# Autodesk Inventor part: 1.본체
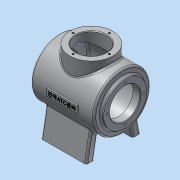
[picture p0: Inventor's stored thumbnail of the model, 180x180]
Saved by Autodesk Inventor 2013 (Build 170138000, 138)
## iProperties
Created: 2015-01
Part Number: 1.본체
Material: 알루미늄 6061
Document SubType Name: Modeling
Designer: dgall
Density: 2.71 g/cm^3
Mass: 1020.74 g
Surface Area: 1061.21 cm^2
Volume: 376.657 cm^3
Author: dgall
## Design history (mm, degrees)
sketch "스케치1"
  geometry: C1 r 50 at (0, 0); 1 further point
  constraints: 1 centre point, 1 coincident
  dimensions: "d0" = 100 diameter of C1
extrude "돌출1" new body sketch "스케치1" stored distance "d2" = 112; taper "d3" = 0 deg
sketch "스케치2"
  geometry: C1 r 38 at (0, 0); 1 further point
  constraints: 1 centre point, 1 coincident
  dimensions: "d4" = 76 diameter of C1
extrude "돌출2" join sketch "스케치2" stored distance "d6" = 122; taper "d7" = 0 deg
sketch "스케치3"
  geometry: L1 (34, -80)-(48, -80); L2 (48, -80)-(39.336, -30.865); L3 (34, -80)-(27.282, -41.901); A1 r 50 centre (0, 0) between (39.336, -30.865) and (27.282, -41.901) reference; 1 further point
  constraints: 6 end point, 2 point on circle, 1 horizontal
  dimensions: "d8" = 14 distance of L1.start L1.end; "d10" = 80 distance from line of L1 A1.centre; "d11" = 80 deg angle of L1 L3; "d12" = 100 deg angle of L1 L2; "d13" = 48 horizontal distance of L1.end point (0, 0)
extrude "돌출3" join sketch "스케치3" stored distance "d14" = 80; taper "d15" = 0 deg
node "작업 평면1"
sketch "스케치4"
  geometry: L1 (-101, 86)-(-101, 10) reference; C1 r 38 at (-39, 48); 1 further point
  constraints: 1 centre point, 1 horizontal alignment
  dimensions: "d83" = 76 diameter of C1; "d85" = 62 distance from line of L1 C1.centre
extrude "돌출4" join sketch "스케치4" stored distance "d19" = 80; taper "d20" = 0 deg
node "작업 평면3"
sketch "스케치12"
  geometry: C1 r 45 at (0, 0); 1 further point
  constraints: 1 centre point, 1 coincident
  dimensions: "d111" = 90 diameter of C1
extrude "돌출7" cut sketch "스케치12" distance "d113" = 97; taper "d114" = 0 deg
hole "구멍1" diameter "d27" = 54; stored, may be unused: countersink angle "d31" = 90 deg, drill point angle "d33" = 118 deg; dims "d25" = 10, "d26" = 10, "d28" = 6, "d29" = 4, "d30" = 2, "d32" = 8
sketch "스케치7"
  geometry: C1 r 27 at (0, 0) reference; 1 further point
  constraints: 1 vertical alignment
  dimensions: "d51" = 32 distance of C1.centre point (0, 32)
hole "구멍4" sketch "스케치7" at (0, 32) diameter "d52" = 3.459; stored, may be unused: countersink angle "d56" = 90 deg, drill point angle "d58" = 118 deg; dims "d53" = 8, "d54" = 4, "d55" = 2, "d57" = 10
node "작업 평면2"
sketch "스케치8"
  geometry: L1 (-26, 6)-(28, 6); L2 (28, 6)-(28, -6); L3 (28, -6)-(-26, -6); L4 (-26, -6)-(-26, 6); L5 (-61, 38)-(-61, -38) reference; 3 further points
  constraints: 8 end point, 2 midpoint, 2 parallel, 1 horizontal, 1 horizontal alignment, 1 perpendicular
  dimensions: "d65" = 54 distance of L1.start L1.end; "d67" = 12 distance of L1.end L2.end; "d80" = 62 distance from line of point (1, 6) L5
extrude "돌출6" join sketch "스케치8" stored distance "d68" = 4; taper "d69" = 0 deg
fillet "모깎기1" dims "d72" = 3
fillet "모깎기2" dims "d73" = 3
fillet "모깎기3" dims "d74" = 3
fillet "모깎기5" dims "d76" = 3
chamfer "모따기1" distance "d77" = 1; stored, may be unused: second distance "d78" = 2, angle "d79" = 45 deg
sketch "스케치10"
  geometry: L1 (28, 6)-(-26, 6) reference; L2 (28, -6)-(28, 6) reference; 5 further points
  constraints: 2 midpoint, 1 coincident, 1 horizontal alignment, 1 vertical alignment, 1 other
feature "엠보싱2" sketch "스케치10" dims "d2" = 112, "d81" = 0.5, "d82" = 0
fillet "모깎기6" dims "d106" = 3
hole "구멍7" diameter "d117" = 54; stored, may be unused: countersink angle "d121" = 90 deg, drill point angle "d123" = 118 deg; dims "d115" = 10, "d116" = 10, "d118" = 8, "d119" = 4, "d120" = 2, "d122" = 10
sketch "스케치13"
  geometry: C1 r 27 at (0, 0) reference; 2 further points
  constraints: 1 vertical alignment
  dimensions: "d124" = 32 distance of C1.centre point (0, 32)
hole "구멍8" sketch "스케치13" at (0, 32) diameter "d125" = 3.459; stored, may be unused: countersink angle "d129" = 90 deg, drill point angle "d131" = 118 deg; dims "d126" = 8, "d127" = 4, "d128" = 2, "d130" = 10
fillet "모깎기7" dims "d135" = 3
chamfer "모따기3" distance "d136" = 1; stored, may be unused: second distance "d137" = 2, angle "d138" = 45 deg
node "솔리드1"
mirror "대칭1"
pattern_circular "원형 패턴1" dims angle "d60" = 360 deg
mirror "대칭2"
pattern_circular "원형 패턴4" dims angle "d133" = 360 deg
other parameters: "d16" = -142, "d110" = -7
